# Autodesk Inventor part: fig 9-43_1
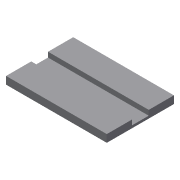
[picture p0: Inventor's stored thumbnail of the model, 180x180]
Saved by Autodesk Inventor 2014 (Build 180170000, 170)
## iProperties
Created: 2013-03
Part Number: fig 9-43_1
Material: Generic
Document SubType Name: Modeling
Designer: CADCIM
Density: 1 g/cm^3
Appearance: Default
Author: CADCIM
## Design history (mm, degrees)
sketch "Sketch1"
  geometry: L1 (-12.966, 10)-(17.034, 10); L2 (17.034, 10)-(17.034, -10); L3 (17.034, -10)-(-12.966, -10); L4 (-12.966, -10)-(-12.966, 10); 1 further point
  constraints: 8 end point, 2 parallel, 1 horizontal, 1 perpendicular
  dimensions: "d0" = 30 distance of L1.start L1.end; "d2" = 20 distance of L1.end L2.end
extrude "Extrusion1" new body sketch "Sketch1" distance "d3" = 2.25; taper "d4" = 0 deg
sketch "Sketch2"
  geometry: L1 (-12.966, 10)-(-12.966, -10) reference; L2 (-12.966, 2.498)-(87.034, 2.498); L3 (87.034, 2.498)-(87.034, -2.502); L4 (87.034, -2.502)-(-12.966, -2.502); L5 (-12.966, -2.502)-(-12.966, 2.498); 1 further point
  constraints: 8 end point, 2 parallel, 1 horizontal, 1 perpendicular, 1 point on line
  dimensions: "d5" = 5 distance of L2.end L3.end; "d7" = 100 distance of L2.start L2.end
extrude "Extrusion2" cut sketch "Sketch2" distance "d8" = 1.5; taper "d9" = 0 deg
body "Solid1"
